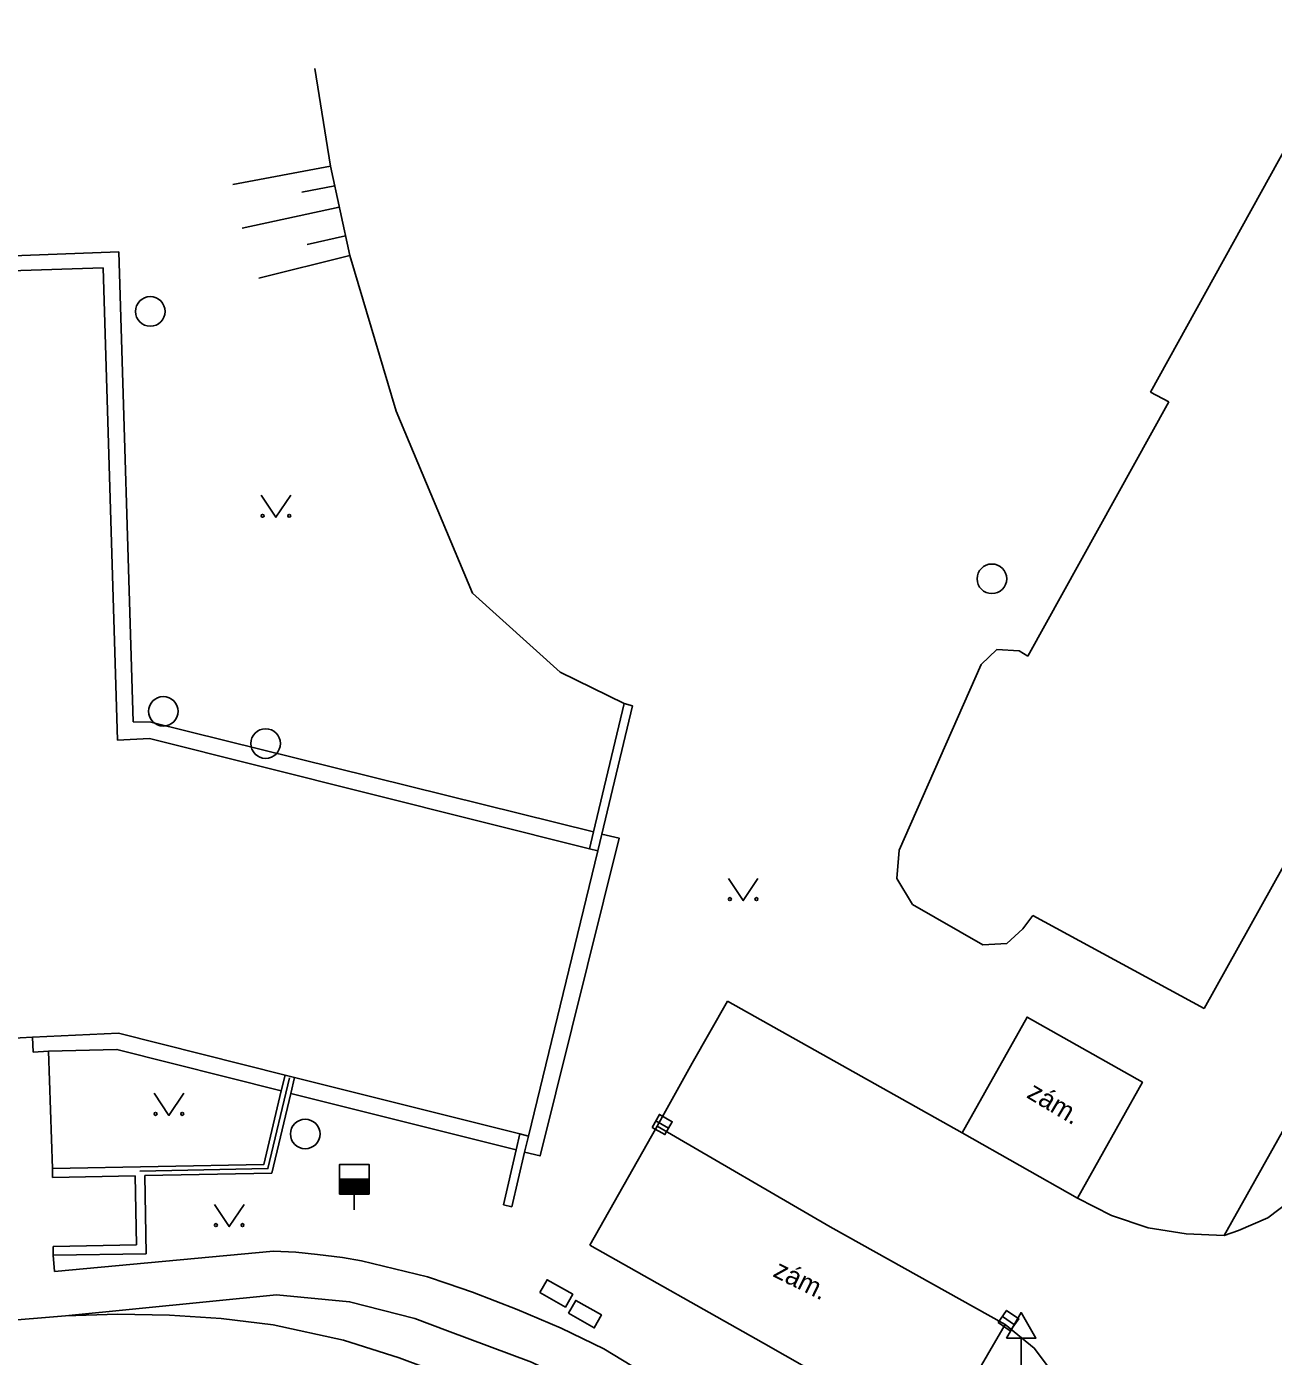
# Model space of a CAD drawing. Extents: x -596024 to -594475, y -1163820 to -1161957.
# Drawn here: x -595761.47 to -595719.31, y -1162979.46 to -1162934.5 of the extents above; entities that cross this region are included whole.
import ezdxf

# ---------------------------------------------------------------- set-up
doc = ezdxf.new("R2010")
doc.units = 0
for name, color, linetype in [('Level 10', 7, 'Continuous'), ('Level 11', 7, 'Continuous'), ('Level 14', 7, 'Continuous'), ('Level 15', 7, 'Continuous'), ('Level 24', 7, 'Continuous'), ('Level 27', 7, 'Continuous'), ('Level 28', 7, 'Continuous'), ('Level 34', 7, 'Continuous'), ('Level 36', 7, 'Continuous'), ('Level 40', 7, 'Continuous'), ('Level 5', 7, 'Continuous'), ('Level 7', 7, 'Continuous'), ('Level 9', 7, 'Continuous')]:
    doc.layers.add(name, color=color, linetype=linetype)

msp = doc.modelspace()

# ---------------------------------------------------------------- linework, layer by layer
at = {"layer": 'Level 10'}
for points in [[(-595738.97, -1162969.55), (-595737.77, -1162967.45)], [(-595737.77, -1162967.45), (-595729.83, -1162971.9)], [(-595740.15, -1162971.67), (-595738.97, -1162969.55)], [(-595742.43, -1162975.7), (-595740.15, -1162971.67)], [(-595729.83, -1162971.9), (-595725.94, -1162974.11)], [(-595717.95, -1162973.03), (-595718.24, -1162973.51), (-595718.76, -1162974.21), (-595719.5, -1162974.77), (-595720.49, -1162975.2), (-595720.97, -1162975.37)], [(-595720.97, -1162975.37), (-595722.26, -1162975.32), (-595723.54, -1162975.11), (-595724.78, -1162974.7), (-595725.94, -1162974.11)], [(-595736.55, -1162979.01), (-595742.43, -1162975.7)], [(-595886.79, -1162989.32), (-595875.89, -1162988.29), (-595874.88, -1162988.19), (-595865.06, -1162987.3), (-595846.54, -1162985.63), (-595834.03, -1162984.4), (-595833.92, -1162984.39), (-595827.57, -1162983.83), (-595811.92, -1162982.46), (-595810.38, -1162982.32), (-595807.74, -1162982.42), (-595798.29, -1162981.55), (-595792.41, -1162981.01), (-595782.08, -1162980.06), (-595767.36, -1162978.71), (-595765.31, -1162978.52), (-595764.65, -1162978.46), (-595760.16, -1162978.09)], [(-595760.16, -1162978.09), (-595758.4, -1162978.03), (-595756.64, -1162978.06), (-595754.89, -1162978.18), (-595753.14, -1162978.39)], [(-595753.14, -1162978.39), (-595750.76, -1162978.91)], [(-595728.38, -1162978.38), (-595730.69, -1162982.35)], [(-595728.38, -1162978.38), (-595727.4, -1162979.18), (-595726.64, -1162980.18), (-595726.29, -1162980.91)], [(-595732.07, -1162987.73), (-595735.04, -1162986.55), (-595737.93, -1162985.18), (-595740.01, -1162984.01), (-595740.71, -1162983.61), (-595743.63, -1162981.78), (-595745.18, -1162980.99), (-595747, -1162980.21), (-595748.87, -1162979.51), (-595750.76, -1162978.91)], [(-595730.69, -1162982.35), (-595736.55, -1162979.01)]]:
    msp.add_lwpolyline(points, dxfattribs=at)
at = {"layer": 'Level 11'}
for points in [[(-595765.52, -1162942.39), (-595758.35, -1162942.12)], [(-595758.35, -1162942.12), (-595757.87, -1162958.01)], [(-595757.87, -1162958.01), (-595757.27, -1162958.02), (-595742.3, -1162961.72)], [(-595742.02, -1162961.8), (-595741.43, -1162961.94), (-595744.11, -1162972.68), (-595744.63, -1162972.55)], [(-595729.83, -1162971.9), (-595727.64, -1162967.99), (-595723.74, -1162970.19), (-595725.94, -1162974.11)], [(-595761.27, -1162968.67), (-595761.25, -1162969.17)], [(-595760.73, -1162969.14), (-595761.25, -1162969.17)], [(-595752.86, -1162970.48), (-595758.42, -1162969.08), (-595760.73, -1162969.14)], [(-595760.73, -1162969.14), (-595760.6, -1162973.11)], [(-595720.97, -1162975.37), (-595717.61, -1162969.37)], [(-595744.92, -1162972.48), (-595752.54, -1162970.57)], [(-595740.15, -1162971.67), (-595734.3, -1162975.08), (-595728.38, -1162978.38)], [(-595760.53, -1162976.59), (-595760.57, -1162976.04)], [(-595760.53, -1162976.59), (-595753.12, -1162975.9)], [(-595753.12, -1162975.9), (-595752.37, -1162975.94), (-595751.63, -1162976.01), (-595750.79, -1162976.12), (-595750.15, -1162976.23)], [(-595750.15, -1162976.23), (-595747.91, -1162976.77)], [(-595747.91, -1162976.77), (-595747.25, -1162977), (-595746.39, -1162977.29), (-595744.88, -1162977.87), (-595743.4, -1162978.51), (-595741.95, -1162979.2)], [(-595760.16, -1162978.09), (-595753.02, -1162977.38)], [(-595736.63, -1162984.12), (-595742.6, -1162980.52), (-595744.4, -1162979.66), (-595747.24, -1162978.59), (-595748.34, -1162978.18), (-595750.55, -1162977.61), (-595753.02, -1162977.38)], [(-595733.17, -1162984.02), (-595735, -1162983.33), (-595735.84, -1162982.91), (-595741.95, -1162979.2)]]:
    msp.add_lwpolyline(points, dxfattribs=at)
at = {"layer": 'Level 14'}
msp.add_lwpolyline([(-595751.72, -1162935.92), (-595751.2, -1162939.22), (-595750.54, -1162942.24), (-595748.98, -1162947.5), (-595746.39, -1162953.66), (-595743.43, -1162956.33), (-595741.27, -1162957.39)], dxfattribs=at)
at = {"layer": 'Level 15'}
for points in [[(-595754.5, -1162939.84), (-595751.2, -1162939.22)], [(-595752.17, -1162940.1), (-595751.05, -1162939.88)], [(-595754.18, -1162941.31), (-595750.9, -1162940.61)], [(-595751.99, -1162941.87), (-595750.69, -1162941.57)], [(-595753.62, -1162943), (-595750.54, -1162942.24)]]:
    msp.add_lwpolyline(points, dxfattribs=at)
at = {"layer": 'Level 24'}
for points in [[(-595744.118, -1162977.301), (-595743.249, -1162977.794), (-595743.002, -1162977.359), (-595743.871, -1162976.866)], [(-595743.148, -1162978.001), (-595742.279, -1162978.494), (-595742.032, -1162978.059), (-595742.901, -1162977.566)]]:
    msp.add_lwpolyline(points, close=True, dxfattribs=at)
at = {"layer": 'Level 27'}
for p, q in [((-595740.198, -1162971.497), (-595739.762, -1162971.743)), ((-595728.475, -1162978.107), (-595728.065, -1162978.393))]:
    msp.add_line(p, q, dxfattribs=at)
for points in [[(-595740.321, -1162971.715), (-595739.885, -1162971.961), (-595739.639, -1162971.525), (-595740.075, -1162971.279)], [(-595728.618, -1162978.313), (-595728.207, -1162978.598), (-595727.922, -1162978.187), (-595728.333, -1162977.902)]]:
    msp.add_lwpolyline(points, close=True, dxfattribs=at)
for centre in [(-595757.29, -1162944.13), (-595728.83, -1162953.17), (-595756.85, -1162957.65), (-595753.39, -1162958.74), (-595752.05, -1162971.94)]:
    msp.add_circle(centre, 0.5, dxfattribs=at)
at = {"layer": 'Level 28'}
for p, q in [((-595750.89, -1162973.47), (-595749.89, -1162973.47)), ((-595750.89, -1162973.52), (-595749.89, -1162973.52)), ((-595750.89, -1162973.57), (-595749.89, -1162973.57)), ((-595750.89, -1162973.62), (-595749.89, -1162973.62)), ((-595750.89, -1162973.67), (-595749.89, -1162973.67)), ((-595750.89, -1162973.72), (-595749.89, -1162973.72)), ((-595750.89, -1162973.77), (-595749.89, -1162973.77)), ((-595750.89, -1162973.82), (-595749.89, -1162973.82)), ((-595750.89, -1162973.87), (-595749.89, -1162973.87)), ((-595750.89, -1162973.92), (-595749.89, -1162973.92)), ((-595750.39, -1162973.97), (-595750.39, -1162974.5))]:
    msp.add_line(p, q, dxfattribs=at)
msp.add_lwpolyline([(-595750.89, -1162973.97), (-595749.89, -1162973.97), (-595749.89, -1162972.97), (-595750.89, -1162972.97)], close=True, dxfattribs=at)
at = {"layer": 'Level 34'}
msp.add_line((-595727.84, -1162978.842), (-595727.84, -1162979.86), dxfattribs=at)
msp.add_lwpolyline([(-595728.34, -1162978.842), (-595727.34, -1162978.842), (-595727.84, -1162977.976)], close=True, dxfattribs=at)
at = {"layer": 'Level 36'}
for points in [[(-595753.54, -1162950.34), (-595753.04, -1162951.09), (-595752.54, -1162950.34)], [(-595737.74, -1162963.3), (-595737.24, -1162964.05), (-595736.74, -1162963.3)], [(-595757.16, -1162970.56), (-595756.66, -1162971.31), (-595756.16, -1162970.56)], [(-595755.12, -1162974.32), (-595754.62, -1162975.07), (-595754.12, -1162974.32)]]:
    msp.add_lwpolyline(points, dxfattribs=at)
for centre in [(-595753.49, -1162951.04), (-595752.591, -1162951.04), (-595737.69, -1162964), (-595736.791, -1162964), (-595757.11, -1162971.26), (-595756.211, -1162971.26), (-595755.07, -1162975.02), (-595754.171, -1162975.02)]:
    msp.add_circle(centre, 0.05, dxfattribs=at)
at = {"layer": 'Level 5'}
for points in [[(-595723.47, -1162946.86), (-595716.62, -1162934.5)], [(-595765.51, -1162942.87), (-595758.88, -1162942.66)], [(-595758.88, -1162942.66), (-595758.4, -1162958.63)], [(-595722.85, -1162947.19), (-595723.47, -1162946.86)], [(-595727.62, -1162955.78), (-595722.85, -1162947.19)], [(-595714.31, -1162954.53), (-595721.65, -1162967.7)], [(-595729.19, -1162956.07), (-595728.66, -1162955.56)], [(-595728.66, -1162955.56), (-595727.91, -1162955.61)], [(-595727.91, -1162955.61), (-595727.62, -1162955.78)], [(-595731.96, -1162962.34), (-595729.19, -1162956.07)], [(-595758.4, -1162958.63), (-595757.32, -1162958.57)], [(-595757.32, -1162958.57), (-595742.44, -1162962.3)], [(-595742.15, -1162962.37), (-595744.5, -1162972.01)], [(-595742.44, -1162962.3), (-595742.15, -1162962.37)], [(-595732.04, -1162963.3), (-595731.96, -1162962.34)], [(-595731.52, -1162964.18), (-595732.04, -1162963.3)], [(-595729.14, -1162965.54), (-595731.52, -1162964.18)], [(-595727.44, -1162964.55), (-595727.78, -1162965)], [(-595721.65, -1162967.7), (-595727.44, -1162964.55)], [(-595727.78, -1162965), (-595728.33, -1162965.5)], [(-595728.33, -1162965.5), (-595729.14, -1162965.54)], [(-595758.36, -1162968.53), (-595761.27, -1162968.67)], [(-595752.73, -1162969.95), (-595758.36, -1162968.53)], [(-595761.27, -1162968.67), (-595762.53, -1162968.73)], [(-595752.41, -1162970.03), (-595752.73, -1162969.95)], [(-595744.79, -1162971.94), (-595752.41, -1162970.03)], [(-595744.5, -1162972.01), (-595744.79, -1162971.94)]]:
    msp.add_lwpolyline(points, dxfattribs=at)
at = {"layer": 'Level 7'}
for points in [[(-595741.27, -1162957.39), (-595742.3, -1162961.72)], [(-595742.02, -1162961.8), (-595740.98, -1162957.46)], [(-595740.98, -1162957.46), (-595741.27, -1162957.39)], [(-595742.3, -1162961.72), (-595742.44, -1162962.3)], [(-595742.15, -1162962.37), (-595742.02, -1162961.8)], [(-595752.73, -1162969.95), (-595752.86, -1162970.48)], [(-595752.54, -1162970.57), (-595752.41, -1162970.03)], [(-595752.86, -1162970.48), (-595753.45, -1162972.97), (-595760.6, -1162973.11)], [(-595753.18, -1162973.27), (-595752.54, -1162970.57)], [(-595744.79, -1162971.94), (-595744.92, -1162972.48)], [(-595744.63, -1162972.55), (-595744.5, -1162972.01)], [(-595744.92, -1162972.48), (-595745.35, -1162974.33)], [(-595745.06, -1162974.4), (-595744.63, -1162972.55)], [(-595760.6, -1162973.11), (-595760.6, -1162973.41)], [(-595760.6, -1162973.41), (-595757.8, -1162973.36)], [(-595757.8, -1162973.36), (-595757.76, -1162975.69)], [(-595757.47, -1162973.34), (-595753.18, -1162973.27)], [(-595757.43, -1162975.99), (-595757.47, -1162973.34)], [(-595745.35, -1162974.33), (-595745.06, -1162974.4)], [(-595757.76, -1162975.69), (-595760.57, -1162975.74)], [(-595760.57, -1162975.74), (-595760.57, -1162976.04)], [(-595760.57, -1162976.04), (-595757.43, -1162975.99)]]:
    msp.add_lwpolyline(points, dxfattribs=at)
at = {"layer": 'Level 9'}
msp.add_lwpolyline([(-595752.58, -1162970.04), (-595753.31, -1162973.11), (-595757.64, -1162973.2)], dxfattribs=at)

# ---------------------------------------------------------------- texts
at = {"layer": 'Level 40'}
for rotation, p in [(329.27, (-595727.69, -1162970.69)), (333.63, (-595736.27, -1162976.74))]:
    msp.add_text('zám.', height=0.65, rotation=rotation, dxfattribs=at).set_placement(p)

doc.saveas('drawing.dxf')
